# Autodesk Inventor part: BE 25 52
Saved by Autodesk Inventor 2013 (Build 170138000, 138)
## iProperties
Created: 2012-12
Part Number: BE 25 52
Material: Générique
Document SubType Name: Modeling
Designer: jost thierry
Density: 1 g/cm^3
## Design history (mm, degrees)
node "BE 25 521"
node "BE 25 52"
node "Base1"
